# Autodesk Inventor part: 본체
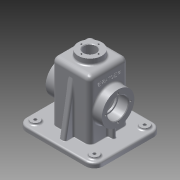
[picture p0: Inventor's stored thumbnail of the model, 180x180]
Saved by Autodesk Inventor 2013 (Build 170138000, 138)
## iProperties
Created: 2016-01
Part Number: 본체
Material: 알루미늄 6061
Document SubType Name: Modeling
Designer: Administrator
Density: 2.71 g/cm^3
Mass: 806.732 g
Surface Area: 909.835 cm^2
Volume: 297.687 cm^3
Author: Administrator
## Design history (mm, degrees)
sketch "스케치1"
  geometry: L1 (65, -57.5)-(-65, -57.5); L2 (-65, -57.5)-(-65, 57.5); L3 (-65, 57.5)-(65, 57.5); L4 (65, 57.5)-(65, -57.5); L5 (65, -57.5)-(-65, 57.5); L6 (-65, -57.5)-(65, 57.5); 1 further point
  constraints: 12 end point, 2 midpoint, 2 parallel, 1 horizontal, 1 perpendicular
  dimensions: "d0" = 115 distance of L1.end L2.end; "d2" = 130 distance of L2.end L3.end
extrude "돌출1" new body sketch "스케치1" distance "d3" = 8; taper "d4" = 0 deg
sketch "스케치2"
  geometry: L1 (32.5, -32.5)-(-32.5, -32.5); L2 (-32.5, -32.5)-(-32.5, 32.5); L3 (-32.5, 32.5)-(32.5, 32.5); L4 (32.5, 32.5)-(32.5, -32.5); L5 (32.5, -32.5)-(-32.5, 32.5); L6 (-32.5, -32.5)-(32.5, 32.5); 1 further point
  constraints: 12 end point, 2 midpoint, 2 parallel, 1 horizontal, 1 perpendicular
  dimensions: "d5" = 65 distance of L2.end L3.end; "d6" = 65 distance of L3.end L1.start
extrude "돌출2" join sketch "스케치2" distance "d7" = 100; taper "d8" = 0 deg
sketch "스케치3"
  geometry: C1 r 27.5 at (-47, 32.5); 1 further point
  constraints: 1 centre point, 1 horizontal alignment
  dimensions: "d9" = 55 diameter of C1; "d10" = 55 distance of point (8, 32.5) C1.centre
extrude "돌출3" join sketch "스케치3" distance "d11" = 15; taper "d12" = 0 deg
sketch "스케치4"
  geometry: L1 (50, 52.5)-(-50, 52.5); L2 (-60, 42.5)-(-60, -42.5); L3 (-50, -52.5)-(50, -52.5); L4 (60, -42.5)-(60, 42.5); L5 (60, 52.5)-(-60, -52.5); L6 (-60, 52.5)-(60, -52.5); A1 r 10 centre (-50, -42.5) between (-60, -42.5) and (-50, -52.5); A2 r 10 centre (50, -42.5) between (50, -52.5) and (60, -42.5); A3 r 10 centre (50, 42.5) between (60, 42.5) and (50, 52.5); A4 r 10 centre (-50, 42.5) between (-50, 52.5) and (-60, 42.5); 1 further point
  constraints: 12 end point, 8 point on circle, 8 point on line, 8 tangent, 4 centre point, 3 equal radius, 2 midpoint, 2 parallel, 1 horizontal, 1 perpendicular
  dimensions: "d13" = 120 distance of L6.end L5.end; "d14" = 105 distance of L6.start L5.end; "d15" = 10 radius of A1
extrude "돌출4" join sketch "스케치4" distance "d16" = 2; taper "d17" = 0 deg
sketch "스케치5"
  geometry: L1 (27.5, 27.5)-(-27.5, 27.5); L2 (-27.5, 27.5)-(-27.5, -27.5); L3 (-27.5, -27.5)-(27.5, -27.5); L4 (27.5, -27.5)-(27.5, 27.5); L5 (27.5, 27.5)-(-27.5, -27.5); L6 (-27.5, 27.5)-(27.5, -27.5); 1 further point
  constraints: 12 end point, 2 midpoint, 2 parallel, 1 horizontal, 1 perpendicular
  dimensions: "d18" = 55 distance of L3.end L2.end; "d19" = 55 distance of L1.end L2.end
extrude "돌출5" cut sketch "스케치5" distance "d20" = 105; taper "d21" = 0 deg
fillet "모깎기1" dims "d22" = 15
sketch "스케치6"
  geometry: C1 r 20 at (0, 0); 1 further point
  constraints: 1 centre point, 1 coincident
  dimensions: "d23" = 40 diameter of C1
extrude "돌출6" join sketch "스케치6" distance "d24" = 10; taper "d25" = 0 deg
sketch "스케치7"
  geometry: C1 r 20 at (0, 0) reference; C2 r 10.5 at (0, 0)
  constraints: 1 centre point, 1 coincident
  dimensions: "d26" = 21 diameter of C2
extrude "돌출7" cut sketch "스케치7" stored distance "d27" = 10; taper "d28" = 0 deg
chamfer "모따기1" distance "d29" = 1; stored, may be unused: second distance "d30" = 2, angle "d31" = 45 deg
fillet "모깎기2" dims "d32" = 8
fillet "모깎기3" dims "d33" = 8
sketch "스케치8"
  geometry: C1 r 20 at (0, 0) reference; 1 further point
  constraints: 1 vertical alignment
  dimensions: "d34" = 14.5 distance of C1.centre point (0, 14.5)
hole "구멍1" sketch "스케치8" at (0, 14.5) diameter "d35" = 2.459; stored, may be unused: countersink angle "d39" = 90 deg, drill point angle "d41" = 118 deg; dims "d36" = 7, "d37" = 4, "d38" = 2, "d40" = 9
sketch "스케치9"
  geometry: C1 r 27.5 at (0, 0) reference; C2 r 17.5 at (0, 0); 1 further point
  constraints: 1 centre point, 1 coincident
  dimensions: "d45" = 35 diameter of C2
extrude "돌출8" cut sketch "스케치9" distance "d46" = 17; taper "d47" = 0 deg
sketch "스케치10"
  geometry: C1 r 17.5 at (0, 0) reference; C2 r 15 at (0, 0); 1 further point
  constraints: 1 centre point, 1 coincident
  dimensions: "d48" = 30 diameter of C2
extrude "돌출9" cut sketch "스케치10" stored distance "d49" = 3; taper "d50" = 0 deg
fillet "모깎기4" dims "d51" = 0.3
chamfer "모따기2" distance "d52" = 1; stored, may be unused: second distance "d53" = 2, angle "d54" = 45 deg
sketch "스케치11"
  geometry: C1 r 27.5 at (0, 0) reference; 2 further points
  constraints: 1 vertical alignment
  dimensions: "d55" = 21 distance of C1.centre point (0, 21)
hole "구멍2" sketch "스케치11" at (0, 21) diameter "d56" = 3.242; stored, may be unused: countersink angle "d60" = 90 deg, drill point angle "d62" = 118 deg; dims "d57" = 8, "d58" = 4, "d59" = 2, "d61" = 10
sketch "스케치12"
  geometry: L1 (-63, 20)-(-63, -20) reference; A1 r 27.5 centre (0, 0) between (-12.49, 24.5) and (-12.49, -24.5) reference; 2 further points
  constraints: 1 horizontal alignment, 1 other
  dimensions: "d66" = 27 distance from line of L1 point (-36, 0)
feature "엠보싱1" sketch "스케치12" dims "d67" = 0.5, "d68" = 0
sketch "스케치13"
  geometry: L1 (0, 0)-(0, 49) reference; L2 (0, 27.5)-(-20, 27.5); L3 (-20, 27.5)-(-20, 21.5); L4 (-20, 21.5)-(0, 21.5); L5 (0, 21.5)-(0, 27.5); 2 further points
  constraints: 8 end point, 2 parallel, 1 horizontal, 1 horizontal alignment, 1 midpoint, 1 perpendicular, 1 point on line
  dimensions: "d69" = 6 distance of L2.end L3.end; "d71" = 20 distance of L2.start L2.end
extrude "돌출10" join sketch "스케치13" distance "d72" = 10; taper "d73" = 0 deg
sketch "스케치14"
  geometry: C1 r 7.5 at (-50, -42.5); C2 r 7.5 at (50, -42.5); C3 r 7.5 at (50, 42.5); C4 r 7.5 at (-50, 42.5); A1 r 15 centre (-50, 42.5) between (-50, 57.5) and (-65, 42.5) reference; A2 r 15 centre (-50, -42.5) between (-65, -42.5) and (-50, -57.5) reference; A3 r 15 centre (50, -42.5) between (50, -57.5) and (65, -42.5) reference; A4 r 15 centre (50, 42.5) between (65, 42.5) and (50, 57.5) reference; 1 further point
  constraints: 4 centre point, 4 coincident
  dimensions: "d74" = 15 diameter of C1; "d75" = 15 diameter of C2; "d76" = 15 diameter of C3; "d77" = 15 diameter of C4
extrude "돌출11" join sketch "스케치14" distance "d78" = 3; taper "d79" = 0 deg
sketch "스케치15"
  geometry: C1 r 7.5 at (0, 0) reference; C2 r 2.5 at (0, 0); 1 further point
  constraints: 1 centre point, 1 coincident
  dimensions: "d80" = 5 diameter of C2
extrude "돌출12" cut sketch "스케치15" stored distance "d81" = 3; taper "d82" = 0 deg
sketch "스케치16"
  geometry: C1 r 7.5 at (0, 0) reference; C2 r 2.5 at (0, 0); 1 further point
  constraints: 1 centre point, 1 coincident
  dimensions: "d83" = 5 diameter of C2
extrude "돌출13" cut sketch "스케치16" stored distance "d84" = 3; taper "d85" = 0 deg
sketch "스케치17"
  geometry: C1 r 7.5 at (0, 0) reference; C2 r 2.5 at (0, 0); 1 further point
  constraints: 1 centre point, 1 coincident
  dimensions: "d86" = 5 diameter of C2
extrude "돌출14" cut sketch "스케치17" stored distance "d87" = 3; taper "d88" = 0 deg
sketch "스케치18"
  geometry: C1 r 7.5 at (0, 0) reference; C2 r 2.5 at (0, 0); 1 further point
  constraints: 1 centre point, 1 coincident
  dimensions: "d89" = 5 diameter of C2
extrude "돌출15" cut sketch "스케치18" stored distance "d90" = 3; taper "d91" = 0 deg
fillet "모깎기5" dims "d92" = 3
fillet "모깎기6" dims "d93" = 3
sketch "스케치19"
  geometry: L1 (52.5, 0)-(52.5, -2) reference; L2 (52.5, -2)-(27.5, -2) reference; L3 (27.5, -2)-(27.5, 103) reference; L4 (27.5, 103)-(10.5, 103) reference; L5 (10.5, 103)-(10.5, 117) reference; L6 (10.5, 117)-(11.5, 118) reference; L7 (11.5, 118)-(13.271, 118) reference; L8 (13.271, 118)-(13.271, 109) reference; L9 (13.271, 109)-(14.5, 108.261) reference; L10 (14.5, 108.261)-(15.73, 109) reference; L11 (15.73, 109)-(15.73, 118) reference; L12 (15.73, 118)-(20, 118) reference; L13 (20, 118)-(20, 111) reference; L14 (23, 108)-(24.5, 108) reference; L15 (32.5, 100)-(32.5, 8) reference; L16 (32.5, 8)-(57.5, 8) reference; L17 (57.5, 8)-(57.5, 0) reference; L18 (57.5, 0)-(52.5, 0) reference; L19 (-52.5, -2)-(-52.5, 0) reference; L20 (-52.5, 0)-(-57.5, 0) reference; L21 (-57.5, 0)-(-57.5, 8) reference; L22 (-57.5, 8)-(-32.5, 8) reference; L23 (-32.5, 8)-(-32.5, 100) reference; L24 (-24.5, 108)-(-23, 108) reference; L25 (-20, 111)-(-20, 118) reference; L26 (-20, 118)-(-15.73, 118) reference; L27 (-15.73, 118)-(-15.73, 109) reference; L28 (-15.73, 109)-(-14.5, 108.261) reference; L29 (-14.5, 108.261)-(-13.271, 109) reference; L30 (-13.271, 109)-(-13.271, 118) reference; L31 (-13.271, 118)-(-11.5, 118) reference; L32 (-11.5, 118)-(-10.5, 117) reference; L33 (-10.5, 117)-(-10.5, 103) reference; L34 (-10.5, 103)-(-27.5, 103) reference; L35 (-27.5, 103)-(-27.5, -2) reference; L36 (-27.5, -2)-(-52.5, -2) reference; L37 (32.5, 93.069)-(47.5, 8); L38 (42.5, 8)-(57.5, 8) reference; A1 r 3 centre (23, 111) between (20, 111) and (23, 108) reference; A2 r 8 centre (24.5, 100) between (32.5, 100) and (24.5, 108) reference; A3 r 8 centre (-24.5, 100) between (-24.5, 108) and (-32.5, 100) reference; A4 r 3 centre (-23, 111) between (-23, 108) and (-20, 111) reference; 1 further point
  constraints: 2 end point, 2 point on line
  dimensions: "d94" = 80 deg angle of L38 L37; "d95" = 10 distance of L16.end L37.end
feature "리브1" sketch "스케치19" dims "d96" = 1, "d97" = 10, "d98" = 0, "d99" = 0, "d100" = 1, "d101" = 1
fillet "모깎기7" dims "d102" = 3
fillet "모깎기8" dims "d103" = 3
fillet "모깎기9" dims "d104" = 3
fillet "모깎기10" dims "d105" = 3
fillet "모깎기11" dims "d106" = 1
fillet "모깎기12" dims "d107" = 3
fillet "모깎기13" dims "d108" = 3
fillet "모깎기15" dims "d110" = 3
node "솔리드1"
mirror "대칭1"
pattern_circular "원형 패턴1" dims angle "d43" = 360 deg
mirror "대칭2"
pattern_circular "원형 패턴2" dims angle "d64" = 360 deg
mirror "대칭3"
mirror "대칭4"
mirror "대칭5"
node "절단 모서리 투영1"
